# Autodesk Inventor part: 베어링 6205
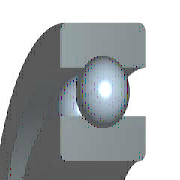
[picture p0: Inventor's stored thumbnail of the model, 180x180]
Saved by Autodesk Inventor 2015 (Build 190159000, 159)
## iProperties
Created: 2012-02
Part Number: 베어링 6205
Material: 강철, 연강
Description: 깊은 그루브 볼 베어링
Document SubType Name: Modeling
Standard: KS B 2023
Designer: mduedu
Standards Organization: KS
Language: ko-KR
Size Designation: 6205 - 25 x 52 x 15
Categories: <MemberInstance><Categories><Category DisplayName="샤프트 부품" InternalName="7f7aeb1f-a693-4053-b835-cee3144e0d98" Mnemonic="SHFT"><Category DisplayName="베어링" Inter
Density: 1 g/cm^3
Appearance: 노란색
IsCustomPart: 1
Author: mduedu
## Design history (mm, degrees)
sketch "스케치" dims "d0" = 7.02 (= -0.26 x WD + 0.26 x BD)
  geometry: L1 (3.99, 19.25)-(11.01, 19.25); L2 (7.5, 19.25)-(7.5, 15.74); L3 (7.5, 19.25)-(7.5, 22.76); L4 (4.892, 16.901)-(0, 16.901); L5 (0, 12.5)-(15, 12.5); L6 (4.892, 21.599)-(0, 21.599); L7 (0, 26)-(15, 26); L8 (15, 12.5)-(15, 16.901); L9 (10.108, 16.901)-(15, 16.901); L10 (10.108, 21.599)-(15, 21.599); L11 (15, 26)-(15, 21.599); L12 (-1.4, 0)-(8.4, 0) reference; L13 (0, -0.3)-(0, 5.3) reference
  constraints: 22 end point, 4 point on line, 2 collinear, 2 perpendicular, 2 symmetric about line, 1 midpoint, 1 parallel, 14 other
  dimensions: "d9" = 25 diameter of L5 L12 (= WD); "d11" = 52 diameter of L7 L12 (= BD); "d12" = 15 distance between parallel lines of L8 L13 (= KB); "d13" = 33.802 diameter of L9 L12 (= 0.326 x BD + 0.674 x WD)
revolve "본체" stored, may be unused: angle "d6" = 90 deg
revolve "볼" stored, may be unused: angle "d7" = 90 deg
pattern_circular "IDS_ARRAYBALL[SIMPL:T]" dims angle "d3" = 360 deg
body "Solid1"
fillet "모깎기1" dims "d1" = 1 (= KRS)
other parameters: "WD" = 25 [user parameter; used in 5 equation terms], "BD" = 52 [user parameter; used in 5 equation terms], "KB" = 15 [user parameter; used in 1 equation term], "KRS" = 1 [user parameter; used in 1 equation term], "d4" = 0, "d5" = 0, "d8" = 0, "d14" = 0, "d15" = 0, "BBA" = 0 [user parameter], "BC0" = 7800000 [user parameter], "BC" = 1.4e+07 [user parameter], "BR" = 26 (= 0.5 x BD) [user parameter], "WR" = 12.5 (= 0.5 x WD) [user parameter]
